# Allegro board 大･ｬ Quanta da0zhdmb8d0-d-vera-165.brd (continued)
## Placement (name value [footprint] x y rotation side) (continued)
PC1239  22u/6.3V_6  [C0603]  84.5 89.14 270 top
PC1240  22u/6.3V_6  [C0603]  31.72 35.72 315 bottom
PC1241  22u/6.3V_6  [C0603]  34 38.01 315 bottom
PC1242  22u/6.3V_6  [C0603]  32.86 36.86 315 bottom
PC1243  22u/6.3V_6  [C0603]  86.63 87.17 180 top
PC1244  22u/6.3V_6  [C0603]  82.57 89.11 270 bottom
PC1245  22u/6.3V_6  [C0603]  80.86 89.08 270 bottom
PC1246  22u/6.3V_6  [C0603]  86.63 88.68 180 top
PC1247  22u/6.3V_6  [C0603]  131.02 87.97 180 top
PC1248  22u/6.3V_6  [C0603]  129.65 82.42 180 top
PC1249  22u/6.3V_6  [C0603]  170.11 74.59 180 top
PC1250  22u/6.3V_6  [C0603]  149.08 85.71 180 top
PC1251  22u/6.3V_6  [C0603]  54.19 84.48 0 top
PC1252  22u/6.3V_6  [C0603]  54.19 86.08 0 top
PC1253  22u/6.3V_6  [C0603]  54.2 87.51 0 top
PC1254  22u/6.3V_6  [C0603]  60.75 86.19 90 bottom
PC1255  22u/6.3V_6  [C0603]  54.19 82.97 0 top
PC1256  22u/6.3V_6  [C0603]  60.34 89.57 270 top
PC1257  22u/6.3V_6  [C0603]  58.92 89.57 270 top
PC1258  0.1U/16V_4  [C0402]  52.16 22.64 270 bottom
PC1259  0.1U/16V_4  [C0402]  51.73 23.71 270 top
PC1260  0.1U/16V_4  [C0402]  50.68 23.73 270 top
PC1261  0.1U/16V_4  [C0402]  48.04 22.25 180 bottom
PC1262  0.1U/16V_4  [C0402]  46.57 25.67 270 top
PC1263  0.1U/16V_4  [C0402]  46.83 30.39 0 bottom
PC1264  0.1U/16V_4  [C0402]  66.99 70.61 90 top
PC1265  0.1U/16V_4  [C0402]  73.59 84.28 180 top
PC1266  0.1U/16V_4  [C0402]  77.11 77.64 270 top
PC1267  0.1U/16V_4  [C0402]  79.62 65.11 90 top
PC1268  0.1U/16V_4  [C0402]  100.68 33.18 90 top
PC1269  0.1U/16V_4  [C0402]  100.55 35.47 90 top
PC1270  0.1U/16V_4  [C0402]  84.14 57.74 90 top
PC1271  0.1U/16V_4  [C0402]  102.33 93.89 180 bottom
PC1272  0.1U/16V_4  [C0402]  54.96 72.75 270 top
PC1273  0.1U/16V_4  [C0402]  25.62 53.5 180 top
PC1274  0.1U/16V_4  [C0402]  42.51 49.69 270 top
PC1275  0.1U/16V_4  [C0402]  217.39 30.01 180 top
PC1276  0.1U/16V_4  [C0402]  22.45 57.44 0 top
PC1277  *0.1U/16V_4  [C0402]  52.54 19.1 90 top
PC1278  *0.1U/16V_4  [C0402]  49.62 49.56 180 top
PC1279  *0.1U/16V_4  [C0402]  98.39 87.28 0 bottom
PC1280  *0.1U/16V_4  [C0402]  208.63 23.27 90 top
PC1281  0.1u/25V_4  [C0402]  192.17 34.88 270 bottom
PC1282  0.1u/25V_4  [C0402]  198.91 34.64 90 bottom
PC1283  0.1u/25V_4  [C0402]  44.77 29.75 270 top
PC1284  0.1u/25V_4  [C0402]  45.73 32.36 90 top
PC1285  0.1u/25V_4  [C0402]  60.32 69.62 270 bottom
PC1286  0.1u/25V_4  [C0402]  63.85 94.95 180 bottom
PC1287  0.1u/25V_4  [C0402]  81.42 76 90 top
PC1288  0.1u/25V_4  [C0402]  75.83 88.64 180 top
PC1289  0.1u/25V_4  [C0402]  170.28 36.93 180 top
PC1290  0.1u/25V_4  [C0402]  165.72 31.09 90 bottom
PC1291  0.1u/25V_4  [C0402]  175.35 42.07 90 top
PC1292  0.1u/25V_4  [C0402]  55.38 27.81 180 bottom
PC1293  0.1u/25V_4  [C0402]  63.46 22.13 0 top
PC1294  *0.1u/25V_4  [C0402]  184.98 40.19 0 top
PC1295  0.01U/50V_4  [C0402]  194.82 39.49 90 bottom
PC1296  0.01U/50V_4  [C0402]  193.48 36.94 180 bottom
PC1297  0.01U/50V_4  [C0402]  197.95 34.64 270 bottom
PC1298  0.01U/50V_4  [C0402]  50.43 28.47 90 top
PC1299  0.01U/50V_4  [C0402]  83.13 57.74 90 top
PC1300  0.01U/50V_4  [C0402]  83.61 61.68 270 top
PC1301  0.01U/50V_4  [C0402]  52.44 68.66 180 top
PC1302  0.01U/50V_4  [C0402]  102.33 92.87 180 bottom
PC1303  0.01U/50V_4  [C0402]  53.43 72.55 180 top
PC1304  0.01U/50V_4  [C0402]  27.78 56.68 90 top
PC1305  0.01U/50V_4  [C0402]  41.24 49.69 270 top
PC1306  0.01U/50V_4  [C0402]  213.96 26.83 0 top
PC1307  0.01U/50V_4  [C0402]  217.39 26.83 180 top
PC1308  0.01U/50V_4  [C0402]  213.33 29.5 90 top
PC1309  0.01U/50V_4  [C0402]  20.92 55.02 0 top
PC1310  0.01U/50V_4  [C0402]  23.33 53.55 0 top
PC1311  0.01U/50V_4  [C0402]  24.35 57.44 0 top
PC1312  *0.01U/50V_4  [C0402]  50 52.1 180 top
PC1313  1U/6.3V_4  [C0402]  48.35 24.54 270 top
PC1314  1U/6.3V_4  [C0402]  48.49 28.47 90 top
PC1315  1U/6.3V_4  [C0402]  61.74 73.03 90 top
PC1316  1U/6.3V_4  [C0402]  74.44 78.62 0 top
PC1317  1U/6.3V_4  [C0402]  63.21 81.74 270 bottom
PC1318  1U/6.3V_4  [C0402]  200.94 36.29 180 top
PC1319  1U/6.3V_4  [C0402]  104.87 35.85 90 top
PC1320  10u/6.3V_4  [C0402_2]  74.16 77.3 0 top
PC1321  10u/6.3V_4  [C0402_2]  69.31 70.39 0 top
PC1322  10u/6.3V_4  [C0402_2]  62.07 85.76 270 bottom
PC1323  10u/6.3V_4  [C0402_2]  71.98 83.24 90 top
PC1324  10u/6.3V_4  [C0402_2]  68.19 73.31 180 top
PC1325  10u/6.3V_4  [C0402_2]  63.16 79.74 270 bottom
PC1326  22nF/16V_4  [C0402]  54.77 25.8 180 top
PC1327  *22nF/16V_4  [C0402]  192.06 41.99 90 bottom
PC1328  *22nF/16V_4  [C0402]  193.07 41.98 90 bottom
PC9091  270p/50V_4  [C0402]  191.97 33.15 90 bottom
PC9093  470p/50V_4  [C0402]  192.36 32.32 90 top
PC9094  470p/50V_4  [C0402]  52.28 26.12 180 top
PC9095  470p/50V_4  [C0402]  189.22 39.5 270 top
PC9096  470p/50V_4  [C0402]  199.16 43.61 270 bottom
PC9097  2200P/50V_4  [C0402]  195.39 41.37 180 bottom
PC9098  2200P/50V_4  [C0402]  189.92 33.98 90 bottom
PC9099  2200P/50V_4  [C0402]  195.06 34.64 90 bottom
PC9100  4.7uF/10V_4  [C0402_2]  172.51 39.26 180 bottom
PC9101  4.7uF/10V_4  [C0402_2]  159.32 31.26 270 top
PC9102  4.7uF/10V_4  [C0402_2]  178.23 38.01 90 bottom
PC9103  *4.7uF/10V_4  [C0402_2]  187.26 38.81 270 top
PC9104  47P/50V_4  [C0402]  193.48 37.9 180 bottom
PC9105  47P/50V_4  [C0402]  196.74 39.49 90 bottom
PC9106  33P/50V_4  [C0402]  196.02 34.64 270 bottom
PC9107  0.15U/10V_4  [C0402]  200.84 32.07 90 top
PC9108  0.18U/10V_4  [C0402]  190.15 32.43 180 top
PC9109  0.18U/10V_4  [C0402]  194.62 42.65 0 top
PC9110  0.22u/10V_4  [C0402]  69.56 72.04 270 top
PC9111  0.47u/6.3V_4  [C0402]  77.54 82.02 270 bottom
PC9112  2.2u/10V_4  [C0402]  70.99 71.89 90 top
PC9113  2.2u/10V_4  [C0402]  73.6 81.16 90 top
PC9114  2.2u/10V_4  [C0402]  60.72 73.03 90 top
PC9115  3300P/50V_4  [C0402]  193.48 38.86 180 bottom
PC9116  3300P/50V_4  [C0402]  199.11 41.19 180 bottom
PC9117  330P/50V_4  [C0402]  193.48 39.83 180 bottom
PC9118  330P/50V_4  [C0402]  193.13 34.64 270 bottom
PC9119  330P/50V_4  [C0402]  198.55 41.6 180 top
PC9120  390P/50V_4  [C0402]  199.23 42.16 0 bottom
PC9121  390P/50V_4  [C0402]  190.79 38.93 180 bottom
PC9122  4700p/25V_4  [C0402]  56.28 29.93 180 bottom
PC9123  4700p/25V_4  [C0402]  199.62 39.49 270 bottom
PC9124  *15u/25V_7343H1.0  [CC7343]  183.23 30.89 270 bottom
PD1  *PDZ5.6B  [DSM]  70.96 19.85 0 top
PD2  *PDZ5.6B  [DSM]  70.96 21.88 0 top
PD3  P4SMAFJ20A  [D-3_8X2_5]  28.92 68.74 90 bottom
PD4  BAT54CW  [UMT_213-3-1_3]  48.81 32.63 0 bottom
PJ2  50458-00801-V02_Header  [50458-00801-V02-8P-L]  66.39 15.65 180 bottom
PL1  0.47uH_7x7x3  [CHOKE-PCMC063T-3R3MN-SMT]  73.18 67.34 0 bottom
PL2  1uH_7x7x3  [CHOKE-PCMC063T-3R3MN-SMT]  57.33 81.41 180 bottom
PL3  2.2uH_7x7x3  [CHOKE-PCMC063T-3R3MN-SMT]  47.62 17.25 90 bottom
PL4  0.15uH_7x7x3  [CHOKE-PCMC063T-3R3MN-SMT]  160.97 38.04 180 bottom
PL5  0.15uH_7x7x3  [CHOKE-PCMC063T-3R3MN-SMT]  177.29 49.52 90 bottom
PL6  *0.15uH_7x7x3  [CHOKE-PCMC063T-3R3MN-SMT]  185.36 49.11 90 bottom
PL7  0.68uH_7x7x3  [CHOKE-PCMC063T-3R3MN-SMT]  152.31 30.96 180 bottom
PL8  2.2uH_7x7x3  [CHOKE-PCMC063T-3R3MN-SMT]  57.27 90.94 0 bottom
PL9  1uH_7x7x3  [CHOKE-PCMC063T-3R3MN-SMT]  69.53 89.67 270 bottom
PL10  2.2uH_7x7x3  [CHOKE-PCMC063T-3R3MN-SMT]  81.42 83.16 270 bottom
PQ1  TPCA8109  [POWER-5X5-1_27-5P]  60.9 27.87 180 bottom
PQ2  CSD87330Q3D  [SON8-3_3X3_3]  53 15.19 0 bottom
PQ3  CSD87330Q3D  [SON8-3_3X3_3]  44.14 24.52 0 bottom
PQ129  PJA138K  [SOT23_213-3_3-2]  27.27 60.1 180 top
PQ130  AO3402  [SOT23_213-3_3-2]  32.73 70.26 0 top
PR1  0.01_1%_0612  [RC3216]  57.22 23.53 0 bottom
PR2  0.02_1%_0612  [RC3216]  42.64 32.37 180 bottom
PR3  2.2_5%_6  [R0603]  177.54 44.8 180 top
PR4  *2.2_5%_6  [R0603]  185.83 44.28 180 top
PR5  2.2_5%_6  [R0603]  165.32 37.56 270 top
PR6  *SHORT_2  [S0201]  69.32 22.34 270 bottom
PR7  *SHORT_2  [S0201]  67.34 22.33 270 bottom
PR8  *0_5%_4  [R0402]  31.97 60.05 180 top
PR9  *SHORT_4  [S0402]  178.66 75.22 0 bottom
PR10  *SHORT_4  [S0402]  193.21 41.99 90 top
PR11  *SHORT_4  [S0402]  192.25 41.99 90 top
PR12  1K_1%_4  [R0402]  199.49 31.78 180 bottom
PR13  *2.2_5%_6  [R0603]  42.79 21.8 180 bottom
PR14  150/F_4  [R0402]  185.77 74.79 0 bottom
PR15  30K_1%_4  [R0402]  177.51 82.46 0 bottom
PR19  *10K_1%_4  [R0402]  77.57 87.47 270 top
PR20  100K_1%_4  [R0402]  54.34 32.47 180 bottom
PR21  *SHORT_4  [S0402]  62.3 75.55 270 top
PR22  *100K_1%_4  [R0402]  53.71 28.85 0 top
PR23  *SHORT_2  [S0201]  60.24 83.83 180 top
PR24  *SHORT_2  [S0201]  57.3 86.73 90 top
PR25  *SHORT_2  [S0201]  57.26 85.39 270 top
PR26  *SHORT_2  [S0201]  67.05 94.85 90 top
PR27  *SHORT_2  [S0201]  66.29 94.84 90 top
PR28  *SHORT_2  [S0201]  78.03 86.12 0 top
PR29  *SHORT_2  [S0201]  77.13 86.06 90 top
PR30  *SHORT_2  [S0201]  73.75 70.45 270 top
PR31  *SHORT_2  [S0201]  72.31 70.44 270 top
PR32  *SHORT_2  [S0201]  102.84 87.28 90 bottom
PR33  *SHORT_4  [S0402]  198.92 32.07 90 top
PR34  *SHORT_4  [S0402]  190.15 34.35 0 top
PR35  *SHORT_4  [S0402]  172.87 36.78 180 bottom
PR36  *SHORT_4  [S0402]  64.48 78.77 0 top
PR37  *SHORT_4  [S0402]  98.01 93 180 bottom
PR38  *SHORT_4  [S0402]  76.27 85.05 0 top
PR39  *SHORT_4  [S0402]  73.07 82.94 270 top
PR40  *SHORT_4  [S0402]  47.59 46.77 0 top
PR41  *SHORT_4  [S0402]  78.96 72.8 180 top
PR42  *SHORT_4  [S0402]  200.75 40.67 180 top
PR43  *SHORT_4  [S0402]  54.46 29.62 0 bottom
PR44  *SHORT_4  [S0402]  52 30.99 90 bottom
PR45  *SHORT_4  [S0402]  51.02 30.99 90 bottom
PR46  *SHORT_4  [S0402]  52.98 31 90 bottom
PR47  *SHORT_4  [S0402]  53.95 30.99 90 bottom
PR48  *SHORT_4  [S0402]  68.17 72.12 0 top
PR49  *SHORT_4  [S0402]  177.01 38.98 0 top
PR50  *SHORT_4  [S0402]  69.82 69.25 0 top
PR51  *SHORT_4  [S0402]  65.02 73.31 270 top
PR52  *SHORT_4  [S0402]  69.82 67.09 0 top
PR53  *SHORT_4  [S0402]  66.72 77.48 90 top
PR54  *SHORT_4  [S0402]  68.93 83.35 90 top
PR55  *SHORT_4  [S0402]  104.49 31.02 0 top
PR56  *SHORT_4  [S0402]  196.94 43.72 90 top
PR57  *SHORT_4  [S0402]  195.98 43.72 90 top
PR58  *SHORT_4  [S0402]  189.66 36.88 0 top
PR59  *SHORT_4  [S0402]  189.66 35.92 0 top
PR60  *SHORT_4  [S0402]  196.02 31.34 270 top
PR61  *SHORT_4  [S0402]  197 31.33 270 top
PR62  *SHORT_4  [S0402]  81.07 66.33 180 top
PR63  *SHORT_4  [S0402]  200.74 39.18 180 top
PR64  *SHORT_4  [S0402]  74.47 82.94 180 top
PR65  *SHORT_4  [S0402]  177.15 37.5 90 bottom
PR66  *SHORT_4  [S0402]  77.33 79.05 180 top
PR67  *SHORT_4  [S0402]  73.34 85.26 0 top
PR68  *SHORT_4  [S0402]  63.34 85.76 270 top
PR69  *SHORT_4  [S0402]  67.41 69.14 180 top
PR70  *SHORT_4  [S0402]  165.59 29.29 90 top
PR71  *0_5%_4  [R0402]  82.92 66.33 180 top
PR72  *0_5%_4  [R0402]  102.58 31.02 180 top
PR73  *0_5%_4  [R0402]  104.49 29.88 0 top
PR74  *0_5%_4  [R0402]  76.75 74.43 90 top
PR75  *0_5%_4  [R0402]  64.89 75.7 0 top
PR76  *0_5%_4  [R0402]  64.99 74.71 0 top
PR77  *0_5%_4  [R0402]  64.71 77.81 180 top
PR78  *0_5%_4  [R0402]  46.32 48.29 90 top
PR79  *0_5%_4  [R0402]  99.66 88.43 0 bottom
PR80  *0_5%_4  [R0402]  99.66 90.46 0 bottom
PR81  *0_5%_4  [R0402]  99.66 89.44 0 bottom
PR82  *0_5%_4  [R0402]  217.39 27.85 0 top
PR83  *0_5%_4  [R0402]  45.23 48.32 90 top
PR84  *0_5%_4  [R0402]  185.43 37.29 270 bottom
PR85  *0_5%_4  [R0402]  191.25 44.06 90 bottom
PR86  *0_5%_4  [R0402]  52.42 49.31 0 top
PR87  *0_5%_4  [R0402]  52.42 51.85 0 top
PR88  *0_5%_4  [R0402]  52.42 48.29 0 top
PR89  *0_5%_4  [R0402]  52.42 50.33 0 top
PR90  *SHORT_4  [S0402]  74.77 75.47 180 top
PR91  0_5%_4  [R0402]  195.21 44.44 90 bottom
PR92  100K_1%_4  [R0402]  52.36 28.47 90 top
PR93  *100K_1%_4  [R0402]  193.17 44.06 90 bottom
PR94  *100K_1%_4  [R0402]  196.57 45.06 180 bottom
PR95  *100K_1%_4  [R0402]  192.21 44.06 90 bottom
PR96  *100K_1%_4  [R0402]  192.06 44.07 90 top
PR97  100K_1%_4  [R0402]  21.43 53.5 0 top
PR98  100K_1%_4  [R0402]  26.76 65.06 270 top
PR99  100K_1%_4  [R0402]  35.65 70.26 180 top
PR100  100K_1%_4  [R0402]  63.9 70.95 180 top
PR101  100K_1%_4  [R0402]  75.66 74.1 90 top
PR102  100K_1%_4  [R0402]  60.5 70.57 270 top
PR103  100K_1%_4  [R0402]  62.43 77.76 90 top
PR104  100K_1%_4  [R0402]  62.37 70.77 270 top
PR105  100K_1%_4  [R0402]  76.45 83.78 0 top
PR106  100K_1%_4  [R0402]  76.45 82.79 0 top
PR107  100K_1%_4  [R0402]  63.34 83.98 90 top
PR108  100K_1%_4  [R0402]  71.09 85.5 90 top
PR109  100K_1%_4  [R0402]  69.94 85.5 90 top
PR110  100K_1%_4  [R0402]  51.4 28.47 270 top
PR111  100K_1%_4  [R0402]  68.42 85.73 180 top
PR112  *100/F_4  [R0402]  189.48 36.64 0 bottom
PR113  *100/F_4  [R0402]  193.51 35.98 0 bottom
PR114  *100/F_4  [R0402]  196.99 34.64 90 bottom
PR115  *100/F_4  [R0402]  193.7 31.79 0 top
PR116  *100/F_4  [R0402]  195.78 39.49 270 bottom
PR117  *100/F_4  [R0402]  197.91 43.94 270 top
PR118  100/F_4  [R0402]  202.91 34.7 270 top
PR119  100/F_4  [R0402]  65.54 23.45 270 bottom
PR120  1.1K_1%_4  [R0402]  197.43 33.29 180 bottom
PR121  1.1K_1%_4  [R0402]  190.82 35.75 90 bottom
PR122  1.1K_1%_4  [R0402]  193.02 44.07 270 top
PR123  *1.1K_1%_4  [R0402]  194.62 44.59 0 top
PR124  1_1%_4  [R0402]  45.46 31.92 0 bottom
PR125  1_1%_4  [R0402]  45.46 32.9 0 bottom
PR126  1_1%_4  [R0402]  54.12 23.71 180 bottom
PR127  1_1%_4  [R0402]  54.1 22.69 180 bottom
PR128  1_1%_4  [R0402]  47.21 28.55 270 top
PR129  1K_1%_4  [R0402]  196.19 43.7 90 bottom
PR130  1K_1%_4  [R0402]  190.18 39.5 270 top
PR131  1K_1%_4  [R0402]  189.96 32.64 0 bottom
PR132  1K_1%_4  [R0402]  62.58 82.2 180 top
PR133  1K_1%_4  [R0402]  54.77 26.78 0 top
PR134  1K_1%_4  [R0402]  78.22 71.51 0 top
PR135  1M_5%_4  [R0402]  76.47 80.65 180 top
PR136  *1M_5%_4  [R0402]  69.94 83.35 270 top
PR137  10K_1%_4  [R0402]  27.27 69.88 90 top
PR138  10K_1%_4  [R0402]  77.13 72.63 0 top
PR139  10K/F_4_3435NTC  [R0402]  173.27 46.93 270 bottom
PR140  10K/F_4_3435NTC  [R0402]  162.59 33.99 180 bottom
PR141  10K/F_4_3435NTC  [R0402]  156.81 28.02 180 bottom
PR142  10K_5%_4  [R0402]  191.16 38.36 270 top
PR143  10K_5%_4  [R0402]  197.08 41.99 90 top
PR144  11K_1%_4  [R0402]  199.88 32.07 90 top
PR145  11K_1%_4  [R0402]  194.62 43.61 180 top
PR146  11K_1%_4  [R0402]  190.15 31.46 0 top
PR147  13K_1%_4  [R0402]  66.85 82.96 180 top
PR148  13K_1%_4  [R0402]  65.96 70.85 90 top
PR149  2K_1%_4  [R0402]  197.63 43.12 180 bottom
PR150  2K_1%_4  [R0402]  193.7 32.75 0 top
PR151  2K_1%_4  [R0402]  197.51 42.16 180 bottom
PR152  2K_1%_4  [R0402]  194.22 43.04 90 bottom
PR153  2K_1%_4  [R0402]  190.79 37.97 180 bottom
PR154  2K_1%_4  [R0402]  189.48 35.68 0 bottom
PR155  2K_1%_4  [R0402]  196.62 32.29 0 bottom
PR156  2K_1%_4  [R0402]  193.78 33.01 0 bottom
PR157  63.4K_1%_4  [R0402]  200.93 34.32 180 top
PR158  10/F_4  [R0402]  202.79 36.61 90 top
PR159  2.49K_1%_4  [R0402]  197.39 41.19 0 bottom
PR160  300K_1%_4  [R0402]  28.19 65.62 180 top
PR161  4.7_4  [R0402]  48.48 31.02 270 top
PR162  470K_4_4700NTC  [R0402]  173.27 48.65 90 bottom
PR163  470K_4_4700NTC  [R0402]  160.83 33.99 180 bottom
PR164  49.9/F_4  [R0402]  202.53 38.39 180 top
PR165  8.25K/F_4  [R0402]  198.66 39.49 270 bottom
PR166  105K/F_4  [R0402]  194.09 34.64 90 bottom
PR167  165K/F_4  [R0402]  200.94 35.32 0 top
PR168  1.47K/F_4  [R0402]  195.05 31.71 90 top
PR169  3.65K/F_4  [R0402]  195.54 33.29 0 bottom
PR170  9.1K/F_4  [R0402]  66.51 85.5 0 top
PR171  604/F_4  [R0402]  35.65 69.12 180 top
PR172  2.21K/F_4  [R0402]  197.63 44.08 180 bottom
PR173  604/F_4  [R0402]  199.49 32.74 0 bottom
PR174  45.3/F_4  [R0402]  204.44 36.36 180 top
PR175  27.4K/F_4  [R0402]  190.79 40.18 0 bottom
PR176  27.4K/F_4  [R0402]  49.46 28.47 270 top
PR177  27.4K/F_4  [R0402]  198.54 42.57 0 top
PR178  162K/F_4  [R0402]  52.28 27.09 180 top
PR179  90.9K/F_4  [R0402]  49.62 31.02 270 top
PR180  249K/F_4  [R0402]  76.47 81.67 180 top
PR181  576/F_4  [R0402]  195.21 42.72 90 bottom
PR182  93.1K/F_4  [R0402]  197.7 39.49 270 bottom
PR183  2.87K/F_4  [R0402]  191.79 36.62 90 bottom
PR184  1.65K/F_4  [R0402]  189.72 38.16 180 top
PR185  97.6K/F_4  [R0402]  192.13 38.73 90 bottom
PR186  536/F_4  [R0402]  190.88 33.98 270 bottom
PR187  7.5K/F_4  [R0402]  75.07 80.63 90 top
PR188  8.06K/F_4  [R0402]  72.53 73.85 0 top
PR189  *SHORT_2  [S0201]  58.38 84.14 180 top
PR190  *2.2_5%_6  [R0603]  156.51 31.41 90 top
PU1  TMP708AIDBVR  [SOT23-5-2_8-95-5P-G708]  182.34 74.46 180 bottom
PU2  FPF2495UCX  [BGA9-FAIRCHILD-FPF2495UCX]  31.46 66.71 90 top
PU3  NX20P5090UK  [BGA15-NXP-NX20P5090UK]  30.83 62.82 0 top
PU4  ISL9237HRZ-T  [QFN32-4X4-4-33P-ISL95853]  49.98 26.17 180 bottom
PU5  ISL95857HRTZ-T  [QFN40-5X5-4-41P-ISL62771-SMT]  196 37.05 180 top
PU6  SIC532CD-T1-GE3  [POWER-4_5X3_5-5-13P]  168.56 37.49 270 bottom
PU7  SIC532CD-T1-GE3  [POWER-4_5X3_5-5-13P]  177.52 42.03 180 bottom
PU8  *SIC532CD-T1-GE3  [POWER-4_5X3_5-5-13P]  186.38 41.11 180 bottom
PU9  ISL95808HRZ-T  [DFN8-2X2-5-9P-ISL6208BCRZ]  163.1 30.35 90 top
PU10  SIZ340DT-T1-GE3  [POWER-3X3-65-10P-0_8H]  159.2 30.22 180 bottom
PU11  SN74AUP1G97DCKR  [SC70-2_1-65-6P-SN74AVC1T45]  103.47 32.8 0 top
PU12  SLG5NT1477VTR  [TDFN9-2X1_5-4]  102.46 35.72 90 top
PU13  *SLG5NT1477VTR  [TDFN9-2X1_5-4]  100.93 86.65 270 bottom
PU14  SLG5NT1477VTR  [TDFN9-2X1_5-4]  81.12 58.88 270 top
PU15  SN74AUP1G97DCKR  [SC70-2_1-65-6P-SN74AVC1T45]  82.09 64.6 0 top
PU16  SLG5NT1477VTR  [TDFN9-2X1_5-4]  81.7 61.81 270 top
PU17  *SLG7NT402VTR  [TDFN8-2X1_5-5-6P]  47.34 51.47 270 top
PU18  SLG7NT402VTR  [TDFN8-2X1_5-5-6P]  100.17 93.12 90 bottom
PU19  SLG5NT1477VTR  [TDFN9-2X1_5-4]  44.42 51.72 180 top
PU20  SLG5NT1477VTR  [TDFN9-2X1_5-4]  26 55.41 180 top
PU21  SLG7NT402VTR  [TDFN8-2X1_5-5-6P]  215.23 28.61 0 top
PU22  SLG7NT402VTR  [TDFN8-2X1_5-5-6P]  23.08 55.28 90 top
PU23  SLG7NT402VTR  [TDFN8-2X1_5-5-6P]  53.18 70.77 0 top
PU50  *SN74LVC1G08DCKR  [SC70-2_1-65-5P]  203.55 23.27 180 top
PU51  AOZ1331DI  [SON14-3X2-4-15P-SMT]  207.87 26.83 0 top
PU3044  CSD87381P  [LGA5-3X2_7]  63.49 88.65 180 bottom
PU3045  CSD87381P  [LGA5-3X2_7]  66.82 69.48 270 bottom
PU3047  CSD87381P  [LGA5-3X2_7]  74.72 86.24 180 bottom
PU3048  CSD87381P  [LGA5-3X2_7]  79 76.77 90 bottom
PU3254  TPS650830ZCGR  [BGA159-TEXAS-TPS650830]  70.22 77.94 270 bottom
Q5  MMBT3904-7-F  [SOT23_213-3_3-2]  181.7 70.52 0 bottom
Q10  AP2331SA-7  [SOT23_213-3_3-2]  22.32 50.58 180 bottom
Q105  PJA3413  [SOT23_213-3_3-2]  98.46 82.32 90 bottom
Q109  DTC144EU  [UMT_213-3-1_3]  13.81 73.82 0 top
Q110  DTC144EU  [UMT_213-3-1_3]  10.25 73.82 0 top
Q111  PJA138K  [SOT23_213-3_3-2]  49.5 49.44 270 bottom
Q112  PJA3434  [SOT23_213-3_3-2]  17.11 13.11 0 bottom
Q113  2N7002K  [SOT23_213-3_3-2]  188.31 19.21 180 top
Q114  PJA3434  [SOT23_213-3_3-2]  16.98 8.29 90 bottom
Q121  DDTC144EUA-7-F  [UMT_213-3-1_3]  10.63 81.69 0 top
Q125  DDTC144EUA-7-F  [UMT_213-3-1_3]  10.63 78.65 0 top
Q127  FDV301N  [SOT23_213-3_3-2]  188.05 23.15 0 top
Q129  *FDV301N  [SOT23_213-3_3-2]  17.52 20.73 0 bottom
Q135  2N7002K  [SOT23_213-3_3-2]  157.65 22.39 180 top
Q136  PJA3434  [SOT23_213-3_3-2]  17.49 16.92 0 bottom
Q137  2N7002KDW  [SOT363-2_1-65-6P]  48.86 63.03 0 top
Q139  2N7002K  [SOT23_213-3_3-2]  39.21 59.72 270 top
QAP1009  2N7002K  [SOT23_213-3_3-2]  70.96 60.74 180 top
QCP4007  PJA3434  [SOT23_213-3_3-2]  25.11 32.16 90 top
QCP4009  MMBT3904-7-F  [SOT23_213-3_3-2]  37.81 22.21 90 bottom
QCP4010  MMBT3904-7-F  [SOT23_213-3_3-2]  101.31 37.37 90 bottom
QCP4011  *MMBT3904-7-F  [SOT23_213-3_3-2]  79.62 20.25 0 bottom
QCP4112  PJA3434  [SOT23_213-3_3-2]  32.48 31.66 0 top
QPM3251  2N7002K  [SOT23_213-3_3-2]  72.1 33.87 0 bottom
QPM3360  2N7002K  [SOT23_213-3_3-2]  92.8 39.53 180 bottom
QPM3362  2N7002K  [SOT23_213-3_3-2]  166.59 22.89 0 bottom
QPM3371  2N7002K  [SOT23_213-3_3-2]  85.18 29.62 90 bottom
QPM3372  PJA3434  [SOT23_213-3_3-2]  81.29 28.42 90 bottom
QPM3373  PJA3434  [SOT23_213-3_3-2]  77.48 28.42 90 bottom
QPM3374  PJA3434  [SOT23_213-3_3-2]  73.75 28.48 270 bottom
QPM3382  2N7002K  [SOT23_213-3_3-2]  69.31 36.61 270 bottom
QPM3383  PJA3434  [SOT23_213-3_3-2]  19.91 51.05 90 top
QPM3384  PJA3434  [SOT23_213-3_3-2]  16.1 51.05 90 top
QPM3387  2N7002K  [SOT23_213-3_3-2]  74.97 39.15 180 top
QPM3388  FDV301N  [SOT23_213-3_3-2]  90.04 68.66 270 top
QPM3389  *2N7002K  [SOT23_213-3_3-2]  118.2 20.86 180 top
QPM3390  PJA138K  [SOT23_213-3_3-2]  96.43 91.33 270 bottom
QPM3391  2N7002K  [SOT23_213-3_3-2]  95.47 36.48 90 bottom
R1A1  *10K_4  [R0402]  27.78 18.32 90 top
R1A2  10K_4  [R0402]  27.78 16.54 90 top
R1A3  *SHORT_6  [S0603]  32.73 15.91 90 top
R1A4  *SHORT_6  [S0603]  31.21 15.91 90 top
R1A4PD1  100K/F_4  [R0402]  77.94 40.42 90 top
R1A5  *SHORT_6  [S0603]  37.94 15.53 270 top
R1A6  *SHORT_6  [S0603]  36.4 15.49 270 top
R1B26  *100K/F_4  [R0402]  18.2 18.52 0 top
R1B27  *0_4  [R0402]  39.57 24.85 270 top
R1B28  *0_4  [R0402]  34.26 23.91 270 top
R1B30  *0_4  [R0402]  36.92 26.45 90 top
R1B32  100K/F_4  [R0402]  15.71 11.46 90 bottom
R1B33  100K/F_4  [R0402]  19.14 21.5 90 top
R1C5  *SHORT_4  [S0402]  15.71 17.18 90 top
R1C10  *1M_4  [R0402]  152.44 20.28 180 top
R1C11  *SHORT_4  [S0402]  18.53 60.13 180 bottom
R1C12  *SHORT_4  [S0402]  18.53 59.11 180 bottom
R1D4  210K_4  [R0402]  36.92 24.67 270 top
R1D7  1K/F_4  [R0402]  16.86 19.08 270 top
R1D9  4.7_4  [R0402]  18.25 11.46 270 top
R1D10  4.7_4  [R0402]  18.71 9.3 270 top
R1D11  *SHORT_4  [S0402]  38.42 24.85 270 top
R1D12  *SHORT_4  [S0402]  33.11 23.91 270 top
R1D13  2K/F_4  [R0402]  31.46 23.53 0 top
R1D18  *0_4  [R0402]  15.71 21.5 90 top
R1D19  *200K_4  [R0402]  16.86 21.5 90 top
R1D21  *300_4  [R0402]  19.7 9.3 270 top
R1D22  *300_4  [R0402]  17.49 12.99 180 top
R1M4  30K/F_4  [R0402]  204.18 19.97 90 top
R1M5  48.7K_4  [R0402]  205.33 19.97 90 top
R2B2  *10K_4  [R0402]  15.71 23.53 270 top
R8A16  *SHORT_6  [S0603]  34.26 61.25 90 top
R11  *SHORT_6  [S0603]  43.4 60.74 0 top
R41  *10K/F_4  [R0402]  23.08 29.75 180 top
R45  49.9_4  [R0402]  100.3 73.45 270 bottom
R46  49.9_4  [R0402]  99.28 73.44 270 bottom
R47  49.9_4  [R0402]  140 52.03 270 top
R48  49.9_4  [R0402]  139.03 51.98 270 top
R49  *49.9_4  [R0402]  143.57 38.94 270 bottom
R56  10K_4  [R0402]  155.24 19.64 0 top
R59  *0_6  [R0603]  18.76 23.91 90 top
R66  1K/F_4  [R0402]  150.64 41.99 0 bottom
R88  1K_2  [R0201]  144.42 38.92 90 bottom
R129  *49.9_4  [R0402]  140.89 39.53 0 bottom
R130  *49.9_4  [R0402]  141.32 39.56 270 top
R131  *49.9_4  [R0402]  140.86 40.5 0 bottom
R132  49.9_4  [R0402]  137.93 39.41 0 top
R133  49.9_4  [R0402]  138.73 37.35 270 top
R134  49.9_4  [R0402]  139.29 39.07 270 top
R136  49.9_4  [R0402]  136.58 39.73 90 top
R138  49.9_4  [R0402]  140.96 40.9 180 top
R217  *1K_2  [R0201]  97.87 73.83 270 bottom
R338  *4.7K_4  [R0402]  48.48 65.82 180 top
R346  *4.7K_4  [R0402]  49.24 59.85 0 top
R527  *SHORT_4  [S0402]  13.68 51.85 270 bottom
R529  20K_4  [R0402]  14.7 51.85 270 bottom
R619  100K/F_4  [R0402]  46.96 58.07 270 bottom
R679  5.9K/F_4  [R0402]  15.84 48.39 180 bottom
R680  2K/F_4  [R0402]  18.23 42.93 0 bottom
R681  10K_4  [R0402]  23.11 39.53 270 top
R682  10K_4  [R0402]  21.84 39.53 270 top
R687  4.7K_4  [R0402]  17.34 49.26 90 bottom
R739  100K/F_4  [R0402]  42.64 58.96 90 top
R771  *SHORT_4  [S0402]  52.04 58.2 90 bottom
R772  *SHORT_4  [S0402]  53.18 58.2 90 bottom
R788  33_4  [R0402]  44.67 58.07 90 bottom
R790  33_4  [R0402]  164.05 22.51 90 bottom
R851  33_4  [R0402]  23.59 20.66 90 top
R865  33_4  [R0402]  79.77 56.22 90 top
R866  33_4  [R0402]  70.58 57.31 90 bottom
R868  33_4  [R0402]  82.64 56.8 0 bottom
R869  33_4  [R0402]  70.45 55.28 180 bottom
R870  33_4  [R0402]  76.22 55.99 180 top
R872  10K_4  [R0402]  181.96 68.11 180 bottom
R873  10K_4  [R0402]  184.5 70.14 270 bottom
R874  10K_4  [R0402]  183.86 68.11 0 bottom
R877  2.2K_4  [R0402]  92.27 48.57 90 bottom
R879  2.2K_4  [R0402]  99.66 41.82 90 bottom
R888  33_4  [R0402]  64.23 55.41 0 top
R889  33_4  [R0402]  64.23 60.99 0 top
R890  33_4  [R0402]  64.23 57.44 0 top
R891  *249K_4  [R0402]  92.93 70.52 0 bottom
R892  *10K_4  [R0402]  97.05 53.3 270 bottom
R894  10K_2  [R0201]  103.23 75.39 0 top
R895  100K_2  [R0201]  77.82 48.67 180 bottom
R896  1K_2  [R0201]  68.8 56.01 90 top
R899  33_4  [R0402]  105.12 40.93 270 top
R900  33_4  [R0402]  102.81 41.31 270 bottom
R936  100K/F_4  [R0402]  25.62 69.88 90 top
R956  *SHORT_6  [S0603]  46.07 55.91 270 top
R957  *SHORT_4  [S0402]  47.97 45.37 180 bottom
R958  *SHORT_4  [S0402]  63.52 57.06 90 bottom
R960  *SHORT_4  [S0402]  59.28 52.87 270 top
R964  *SHORT_4  [S0402]  173.07 26.83 270 top
R977  *SHORT_4  [S0402]  39.72 50.71 0 top
R979  5.11K_4  [R0402]  14.09 53.2 0 bottom
R980  30.9K_4  [R0402]  35.02 43.98 270 top
R981  5.11K_4  [R0402]  34 43.98 90 top
R982  60.4/F_4  [R0402]  28.41 53.75 180 top
R983  150/F_4  [R0402]  17.34 53.91 180 bottom
R984  5.11K_4  [R0402]  17.37 53.75 180 top
R985  30.9K_4  [R0402]  26 51.34 90 top
R986  5.11K_4  [R0402]  26.97 51.72 270 top
R987  60.4/F_4  [R0402]  28.41 52.74 180 top
R988  150/F_4  [R0402]  28.41 50.58 180 top
R999  75K/F_4  [R0402]  31.59 57.44 180 top
R1000  15K/F_4  [R0402]  30.83 55.15 180 top
R1002  *SHORT_4  [S0402]  39.72 51.85 0 top
R1022  180K/F_4  [R0402]  73.37 38.39 180 bottom
R1023  20K_2  [R0201]  75.79 39.02 270 bottom
R1040  SP@100K_2  [R0201]  94.33 60.61 180 bottom
R1041  SP@100K_2  [R0201]  93.95 61.5 180 bottom
R1042  SP@100K_2  [R0201]  94.33 59.85 180 bottom
R1043  SP@100K_2  [R0201]  94.71 58.96 90 bottom
R1044  SP@100K_2  [R0201]  95.47 60.61 180 bottom
R1045  SP@100K_2  [R0201]  95.22 61.5 270 bottom
R1046  SP@100K_2  [R0201]  95.47 59.85 180 bottom
R1047  SP@100K_2  [R0201]  95.47 58.96 90 bottom
R1048  *SHORT_2  [S0201]  95.34 39.4 270 bottom
R1049  *100K_2  [R0201]  83.15 45.88 270 top
R1050  100K_2  [R0201]  82.39 45.88 270 top
R1051  *100K_2  [R0201]  86.07 33.31 90 bottom
R1052  100K_2  [R0201]  83.53 43.85 0 top
R1053  *100K_2  [R0201]  82.52 43.85 180 top
R1054  100K_2  [R0201]  85.31 33.31 270 bottom
R1056  113/F_4  [R0402]  97.52 55.2 180 bottom
R1064  *2.2K_4  [R0402]  102.96 41.38 180 top
R1071  *SHORT_2  [S0201]  75.1 43.42 0 top
R1074  *SHORT_4  [S0402]  77.31 38.13 90 top
R1075  *10K_2  [R0201]  78.33 37.5 90 top
R1076  *SHORT_4  [S0402]  69.31 32.93 0 bottom
R1082  100K_2  [R0201]  27.78 33.82 270 top
R1084  100K_2  [R0201]  32.73 54.9 0 top
R1085  560_4  [R0402]  13.05 76.23 270 top
R1086  1K/F_4  [R0402]  12.03 76.23 90 top
R1097  *4.7K/J_4  [R0402]  98.04 53.3 270 bottom
R1104  *SHORT_2  [S0201]  74.77 42.71 0 bottom
R1105  *SHORT_4  [S0402]  64.23 54.14 180 top
R1106  33_4  [R0402]  99.18 38.54 270 top
R1109  *SHORT_2  [S0201]  83.91 45.88 90 top
R1113  100K_2  [R0201]  98.45 72.69 270 top
R1115  *SHORT_2  [S0201]  133.56 73.52 90 bottom
R1116  *SHORT_2  [S0201]  135.52 71.98 0 top
R1117  *0_2  [R0201]  133.56 74.97 270 bottom
R1118  *SHORT_2  [S0201]  130.34 73.43 180 top
R1119  *SHORT_2  [S0201]  131.12 71.78 90 bottom
R1120  *0_2  [R0201]  128.62 62.01 270 top
R1124  0_4  [R0402]  20.92 20.73 270 bottom
R1129  49.9K/F_4  [R0402]  47.97 46.52 180 bottom
R1131  100K_2  [R0201]  92.74 70.28 90 top
R1134  *100K_2  [R0201]  98.39 40.55 90 bottom
R1138  *0_2  [R0201]  186.78 16.29 0 top
R1139  *SHORT_2  [S0201]  186.78 15.53 180 top
R1141  *100K_2  [R0201]  99.15 52.33 0 bottom
R1142  *100K_2  [R0201]  99.15 53.42 0 bottom
R1143  *100K_2  [R0201]  97.48 55.18 0 top
R1144  100K_2  [R0201]  186.78 14.64 0 top
R1157  100K_2  [R0201]  28.29 27.21 90 bottom
R1158  *SHORT_2  [S0201]  83.28 33.31 270 bottom
R1162  100K_2  [R0201]  34.13 56.93 270 top
R1163  100K_2  [R0201]  34.89 56.93 270 top
R1168  3.3K_4  [R0402]  88.26 42.32 90 top
R1169  3.3K_4  [R0402]  87.29 42.32 90 top
R1178  10K_2  [R0201]  72.31 62.64 90 top
R1179  100K_2  [R0201]  74.77 43.47 180 bottom
R1180  499/F_4  [R0402]  149.32 43.09 0 bottom
R1181  *0_4  [R0402]  37.3 43.98 270 top
R1182  *0_4  [R0402]  36.16 43.98 270 top
R3491  100K_2  [R0201]  188.69 16.8 270 top
R3493  *SHORT_4  [S0402]  31.08 25.05 270 top
R3499  33/F_2  [R0201]  91.24 78 270 top
R3501  *SHORT_2  [S0201]  94.78 84.83 90 top
R3502  *SHORT_2  [S0201]  93.62 84.84 90 top
R3503  33/F_2  [R0201]  91.24 79.24 90 top
R3504  *SHORT_2  [S0201]  97.7 80.72 180 top
R3526  *SHORT_4  [S0402]  72.99 36.61 270 bottom
R3534  *SHORT_6  [S0603]  186.28 70.52 90 bottom
R3535  *SHORT_6  [S0603]  20.92 24.57 0 top
R3550  1K/F_4  [R0402]  9.75 83.73 180 top
R3571  *Short_0805  [S0805]  124.3 77.5 270 top
R3587  100K_2  [R0201]  107.92 72.55 270 top
R3591  100K/F_4  [R0402]  90.26 25.31 180 bottom
R3592  100K/F_4  [R0402]  90.26 24.29 180 bottom
R3593  47K/F_4  [R0402]  81.5 31.78 270 bottom
R3594  47K/F_4  [R0402]  78.07 31.78 270 bottom
R3596  100K/F_4  [R0402]  83.15 26.7 90 bottom
R3597  47K/F_4  [R0402]  85.16 23.4 270 bottom
R3603  *SHORT_4  [S0402]  20.67 57.82 0 top
R3604  10K_2  [R0201]  43.96 45.78 90 top
R3608  10K_2  [R0201]  39.34 49.56 90 top
R3609  1M_2  [R0201]  44.16 44.86 0 top
R3611  1M_2  [R0201]  28.8 48.67 180 top
R3614  1M_2  [R0201]  28.8 49.56 180 top
R3620  *SHORT_4  [S0402]  41.14 51.47 270 top
R4434  100K_2  [R0201]  99.98 75.21 0 top
R5004  560_4  [R0402]  10 76.61 0 top
R5009  *0_2  [R0201]  92.62 56.49 180 bottom
R5010  *SHORT_6  [S0603]  46.19 60.74 0 top
R5018  *SHORT_4  [S0402]  23.69 48.19 180 bottom
R5020  100K_2  [R0201]  190.34 22.13 270 top
R5026  *SHORT_2  [S0201]  90.14 46.13 0 bottom
R5027  *0_2  [R0201]  90.01 41.82 90 bottom
R5037  365/F_4  [R0402]  136.35 41.27 0 top
R5038  9.1K/F_4  [R0402]  18 49.64 0 top
R5039  *SHORT_4  [S0402]  19.27 53.75 0 top
R5040  *SHORT_4  [S0402]  90.39 44.36 0 bottom
R5041  *0_4  [R0402]  28.41 47.66 0 top
R5042  9.1K/F_4  [R0402]  13.68 50.07 90 top
R5043  *SHORT_4  [S0402]  13.68 51.85 90 top
R5049  *10K_4  [R0402]  90.26 26.32 0 bottom
R5050  2K/F_4  [R0402]  88.1 26.32 180 bottom
R5051  *SHORT_4  [S0402]  69.31 33.94 180 bottom
R5057  33_4  [R0402]  111.48 77.06 90 bottom
R5058  33_4  [R0402]  113.83 77.11 90 bottom
R5059  33_4  [R0402]  110.51 76.87 90 bottom
R5060  33_4  [R0402]  109.55 77.38 90 bottom
R5063  *SHORT_4  [S0402]  149.6 25.97 0 top
R5066  *SHORT_4  [S0402]  147.44 23.73 0 top
R5068  *SHORT_4  [S0402]  146.88 21.72 270 top
R5072  *SHORT_4  [S0402]  150.23 24.57 270 top
R5073  10K_4  [R0402]  151.78 25.46 90 top
R5078  *SHORT_4  [S0402]  81.37 50.58 270 bottom
R5079  *43_4  [R0402]  82.39 49.44 270 bottom
R5080  *SHORT_4  [S0402]  76.29 44.86 270 top
R5081  *0_4  [R0402]  75.15 44.86 90 top
R5084  *0_4  [R0402]  76.04 34.7 90 bottom
R5085  *0_6  [R0603]  27.65 26.2 0 top
R5086  *SHORT_6  [S0603]  27.65 27.72 0 top
R5087  *0_6  [R0603]  20.92 25.99 0 top
R5088  10K_4  [R0402]  90.72 66.17 180 top
R5090  *0_4  [R0402]  27.14 21.88 270 bottom
R5091  *0_4  [R0402]  26.13 21.88 270 bottom
R5092  *4.42K/F_4  [R0402]  24.99 29.75 0 top
R5093  *SHORT_4  [S0402]  117.24 18.45 180 top
R5094  *100K/F_4  [R0402]  115.84 18.02 90 top
R5095  100K_2  [R0201]  204.56 11.97 90 top
R5096  100K_2  [R0201]  205.45 11.97 90 top
R5097  100K_2  [R0201]  206.34 11.97 90 top
R5098  *SHORT_4  [S0402]  33.11 35.59 270 top
R5099  *SHORT_4  [S0402]  29.18 34.45 270 top
R5100  *0_4  [R0402]  31.97 35.59 90 top
R5101  *0_4  [R0402]  30.32 34.45 270 top
R5102  100K_2  [R0201]  33.11 34.07 270 top
R5103  *SHORT_4  [S0402]  201.9 14.77 90 top
R5104  *SHORT_4  [S0402]  88.99 34.75 180 bottom
R5106  100K/F_4  [R0402]  155.31 21.37 90 top
R5107  0_2  [R0201]  106.9 71.66 180 bottom
R5108  *4.7K_4  [R0402]  24.27 46.24 90 bottom
R5109  4.7K_4  [R0402]  18.46 49.26 90 bottom
R5110  *4.7K_4  [R0402]  21.38 48.06 180 bottom
R5115  *SHORT_6  [S0603]  23.26 50.63 180 top
R5116  2K/F_4  [R0402]  18.23 41.66 0 bottom
R5117  33_4  [R0402]  194.78 16.54 180 top
R5118  33_4  [R0402]  178.08 88.46 0 top
R5123  *0_4  [R0402]  24.1 49.31 180 bottom
R5124  *0_6  [R0603]  18.97 37.42 180 top
R5125  33_4  [R0402]  64.23 56.42 180 top
R5126  15_4  [R0402]  70.32 47.4 180 bottom
R5127  15_4  [R0402]  70.32 49.44 180 bottom
R5128  15_4  [R0402]  70.32 51.47 180 bottom
R5129  15_4  [R0402]  70.32 45.37 180 bottom
R5130  15_4  [R0402]  70.32 46.39 180 bottom
R5131  15_4  [R0402]  70.32 48.42 180 bottom
R5132  15_4  [R0402]  70.32 50.45 180 bottom
R5133  15_4  [R0402]  70.32 52.48 180 bottom
R5134  15_4  [R0402]  70.32 43.21 180 bottom
R5135  15_4  [R0402]  98.01 60.73 270 bottom
R5136  15_4  [R0402]  97.05 60.73 270 bottom
R5137  0_4  [R0402]  94.78 83.33 270 top
R5138  0_4  [R0402]  93.76 83.33 270 top
R5139  0_4  [R0402]  97.5 78.96 270 top
R5140  *0_4  [R0402]  101.76 40.53 270 bottom
R5141  *0_4  [R0402]  101.59 40.9 270 top
R5142  0_4  [R0402]  103.6 40.42 180 top
R5143  0_4  [R0402]  100.74 40.51 270 bottom
R5144  *0_4  [R0402]  153.79 23.43 270 top
R5145  0_4  [R0402]  154.93 23.43 270 top
R5146  10K_4  [R0402]  96.06 73.82 0 top
R5147  *0_4  [R0402]  98.51 78.96 270 top
R5148  47/F_4  [R0402]  25.11 21.5 180 top
R5149  47/F_4  [R0402]  27.14 21.5 0 top
R5150  100K/F_4  [R0402]  108.57 76.22 270 bottom
R5151  *SHORT_4  [S0402]  153.87 20.86 90 top
R5152  10K_4  [R0402]  149.22 24.57 270 top
R5153  100K/F_4  [R0402]  88.49 31.28 0 bottom
R5154  *0_4  [R0402]  48.48 64.8 0 top
R5155  *0_4  [R0402]  48.48 60.99 180 top
R5157  *10K_4  [R0402]  48.1 58.07 270 bottom
R5158  10K_4  [R0402]  39.21 57.31 0 top
R5159  0_2  [R0201]  94.71 50.07 90 bottom
R5160  2.2_6  [R0603]  178.42 83.8 0 top
R6001  *10/F_4  [R0402]  103.04 38.68 90 top
R6002  *10/F_4  [R0402]  96.88 80.98 0 bottom
R6003  *10/F_4  [R0402]  87.09 82.58 0 top
R6006  *0_4  [R0402]  40.86 61.04 180 top
R6007  *0_4  [R0402]  44.17 64.2 180 top
R6008  *10/F_4  [R0402]  93.44 90.2 0 bottom
R6009  *10/F_4  [R0402]  146.63 38.79 0 bottom
RAP1000  100K_2  [R0201]  103.22 76.23 0 top
RAP1001  10K_2  [R0201]  103.23 74.6 0 top
RAP1002  *10K_2  [R0201]  93.14 71.49 0 bottom
RAP1003  10K_2  [R0201]  101.89 42.57 0 bottom
RAP1004  100K_2  [R0201]  100.87 42.57 180 bottom
RAP1005  10K_2  [R0201]  108.04 73.82 0 top
RAP1008  100K_2  [R0201]  96.46 73.03 270 bottom
RAP1009  4.7K_2  [R0201]  86.58 52.1 180 bottom
RAP1010  4.7K_2  [R0201]  86.55 53.01 180 bottom
RAP1011  10K_2  [R0201]  108.04 74.58 0 top
RAP1013  24.9_4  [R0402]  142.46 41.05 270 bottom
RAP1014  100K_2  [R0201]  93.18 50.07 270 bottom
RAP1016  100K_2  [R0201]  93.95 50.07 270 bottom
RAP1017  162_4  [R0402]  99.84 74.84 0 bottom
RAP1018  80.6_4  [R0402]  99.84 75.85 0 bottom
RAP1019  200_4  [R0402]  99.84 76.87 0 bottom
RAP1021  24.9_4  [R0402]  171.67 82.08 180 top
RAP1023  24.9_4  [R0402]  166.37 82.08 180 top
RAP1025  24.9_4  [R0402]  168.97 82.12 180 top
RAP1026  5.11_4  [R0402]  171.67 84.36 0 top
RAP1027  10/F_4  [R0402]  166.34 84.37 0 top
RAP1028  10/F_4  [R0402]  168.97 84.41 0 top
RAP1029  8.2K/F_4  [R0402]  171.67 86.65 0 top
RAP1030  8.2K/F_4  [R0402]  171.67 85.5 180 top
RAP1031  8.2K/F_4  [R0402]  166.34 86.65 0 top
RAP1032  8.2K/F_4  [R0402]  166.34 85.51 180 top
RAP1033  8.2K/F_4  [R0402]  169 86.65 0 top
RAP1034  8.2K/F_4  [R0402]  168.97 85.55 180 top
RAP1035  *20K_2  [R0201]  90.85 63.86 90 top
RAP1044  1K_2  [R0201]  93.21 81.8 270 bottom
RAP1046  *20K_2  [R0201]  98.34 76.87 270 bottom
RAP1047  2.2K_4  [R0402]  110.98 35.84 90 top
RAP1049  2.2K_4  [R0402]  112.25 35.84 90 top
RAP1050  200_4  [R0402]  95.79 55.2 0 bottom
RAP1051  10K_2  [R0201]  96.87 51.85 180 bottom
RAP1052  10K_2  [R0201]  96.87 51.11 180 bottom
RAP1053  100/F_4  [R0402]  100.3 49.61 270 bottom
RAP1054  200_4  [R0402]  94.78 70.13 0 bottom
RAP1055  100/F_4  [R0402]  111.73 40.93 90 top
RAP1061  100K_2  [R0201]  102.28 81.21 0 bottom
RAP1062  1K_2  [R0201]  148.15 39.86 270 bottom
RAP1064  60.4_4  [R0402]  149.14 40.6 270 bottom
RAP1067  1M_2  [R0201]  113.12 72.68 270 top
RAP1072  20K_4  [R0402]  98.08 78.3 180 bottom
RAP1075  1M_4  [R0402]  92.96 75.43 180 bottom
RAP1077  10K_2  [R0201]  95.65 73.08 270 bottom
RAP1078  20K_4  [R0402]  98.09 79.33 180 bottom
RAP1081  *100K_2  [R0201]  108.04 75.34 0 top
RAP1087  1M_4  [R0402]  124.14 41.4 0 bottom
RAP1088  10M_4  [R0402]  106.27 75.75 180 bottom
RAP1089  *SHORT_4  [S0402]  124.57 39.97 270 bottom
RAP1090  *SHORT_4  [S0402]  123.54 39.96 270 bottom
RAP1091  2.7K/F_4  [R0402]  126.41 41.1 0 bottom
RAP1322  1.5K/F_4  [R0402]  104.11 39.02 270 top
RAP1323  49.9_4  [R0402]  142.59 38.95 90 bottom
RAP1324  *100K_2  [R0201]  148.14 40.97 270 bottom
RAP1325  *SHORT_2  [S0201]  147.99 69.24 180 bottom
RAP1326  *SHORT_2  [S0201]  98.95 71.69 270 bottom
RAP1327  *1K_2  [R0201]  152.11 40.29 0 bottom
RAP1328  *1K_2  [R0201]  147.54 44.1 0 bottom
RAP1330  *1K_2  [R0201]  147.52 43.06 0 bottom
RAP1331  *1K_2  [R0201]  147.54 44.86 0 bottom
RAP1332  1K_2  [R0201]  147.54 45.88 0 bottom
RAP1333  *1K_2  [R0201]  150.59 40.42 0 bottom
RAP1335  *1K_2  [R0201]  147.54 46.9 0 bottom
RAP1336  *1K_2  [R0201]  147.41 49.18 270 bottom
RAP1337  *1K_2  [R0201]  148.99 47.2 90 bottom
RAP1343  150/F_4  [R0402]  150.46 44.1 0 bottom
RAP1344  1K/F_4  [R0402]  150.46 45.12 0 bottom
RAP1351  *SHORT_4  [S0402]  139.21 40.42 180 top
RAP1352  *SHORT_4  [S0402]  139.11 41.38 180 top
RAP1360  *SHORT_2  [S0201]  104.74 9.66 180 bottom
RAP1364  *SHORT_2  [S0201]  97.38 9.3 0 bottom
RAP1376  *SHORT_4  [S0402]  137.1 37.27 0 top
RAP1377  *SHORT_4  [S0402]  137.1 38.23 0 top
RAP1381  *SHORT_4  [S0402]  139.49 39.86 90 bottom
RAP1382  *SHORT_4  [S0402]  138.52 39.89 90 bottom
RAP1383  *SHORT_4  [S0402]  140.68 37.57 0 top
RAP1384  *SHORT_4  [S0402]  140.25 38.92 90 top
RAP1385  *SHORT_4  [S0402]  93.26 83.29 270 bottom
RAP1386  *SHORT_4  [S0402]  93.52 86.04 180 bottom
RAP1387  100K/F_4  [R0402]  93.49 84.97 180 bottom
RAP1405  *SHORT_2  [S0201]  80.74 56.45 90 top
RAP1406  *SHORT_2  [S0201]  76.7 52.84 0 bottom
RAP1407  33_2  [R0201]  68.52 57.95 0 top
RAP1408  33_2  [R0201]  74.77 56.19 90 top
RAP1409  *SHORT_2  [S0201]  82.52 55.79 0 bottom
RAP1410  *SHORT_2  [S0201]  75.68 52.84 0 bottom
RAP1412  *3.3K_4  [R0402]  76.29 57.69 270 top
RAP1413  100K/F_4  [R0402]  75.15 57.69 270 top
RAP1414  100K/F_4  [R0402]  74.01 57.69 270 top
RAP1422  *SHORT_2  [S0201]  54.58 57.56 0 top
RAP1423  *4.7K_4  [R0402]  54.58 56.17 270 top
RAP1424  100K_2  [R0201]  62.86 55.05 90 top
RAP1428  *SHORT_2  [S0201]  99.15 9.43 180 bottom
RAP1429  *SHORT_2  [S0201]  100.17 18.32 90 bottom
RAP1430  100K_2  [R0201]  97.38 85.12 270 bottom
RAP1431  100K_2  [R0201]  100.52 81.73 90 top
RAP1432  *20K_2  [R0201]  97.49 72.1 0 top
RAP1433  *20K_2  [R0201]  98.29 75.73 270 bottom
RAP1434  20K_2  [R0201]  104.39 40.91 90 bottom
RAP1436  20K_2  [R0201]  105.88 40.91 90 bottom
RAP1438  20K_2  [R0201]  105.12 40.91 90 bottom
RAP1440  20K_2  [R0201]  103.65 40.91 90 bottom
RAP1450  100/F_4  [R0402]  146.78 40.93 0 bottom
RAP1451  56_4  [R0402]  146.78 39.91 180 bottom
RAP1452  10K_2  [R0201]  101.77 75.71 180 bottom
RAP1453  100K_2  [R0201]  103.6 42.58 0 bottom
RAP1455  100K_2  [R0201]  97.5 40.55 270 bottom
RAP1457  *SHORT_2  [S0201]  107.66 77.76 270 top
RAP1458  *0_2  [R0201]  108.04 76.87 180 top
RAP1459  *SHORT_2  [S0201]  93.12 72.31 180 bottom
RAP3020  1M_2  [R0201]  108.04 76.11 0 top
RAP3021  *3.3K_4  [R0402]  64.23 58.58 0 top
RAP3023  *3.3K_4  [R0402]  64.23 59.98 0 top
RAP3040  1M_4  [R0402]  91.66 41.87 180 bottom
RAP3041  1M_4  [R0402]  75.02 34.7 270 bottom
RAP3042  *10K_2  [R0201]  72.76 39.76 90 top
RAP3043  *4.7K_4  [R0402]  112.23 33.94 270 top
RAP3044  *4.7K_4  [R0402]  110.96 33.94 270 top
RAP3045  0_4  [R0402]  91.91 89.06 90 top
RAP3046  *0_4  [R0402]  90.9 89.06 90 top
RAP3047  *100K_2  [R0201]  92.68 90.33 180 top
RAP3048  *0_4  [R0402]  98.01 89.7 270 top
RAP3049  10K_2  [R0201]  96.99 89.06 0 bottom
RAP3051  *0_2  [R0201]  95.85 89.06 180 bottom
RAP3052  *0_2  [R0201]  101.47 76.89 270 bottom
RAP3053  4.7K_2  [R0201]  100.17 52.48 0 bottom
RAP3054  4.7K_2  [R0201]  100.17 53.37 0 bottom
RCP4021  100K_2  [R0201]  175.23 20.48 270 top
RCP4029  100K_2  [R0201]  29.18 27.21 270 bottom
RCP4037  10K_2  [R0201]  172.94 23.78 270 bottom
RCP4072  *SHORT_4  [S0402]  89.25 14.38 90 bottom
RCP4074  *0_4  [R0402]  86.58 16.57 270 bottom
RCP4160  100K/F_4  [R0402]  19.65 57.69 180 bottom
RCP4162  100K/F_4  [R0402]  21.56 57.69 0 bottom
RCP4184  2M/F_4  [R0402]  16.81 59.01 180 bottom
RCP4186  2M/F_4  [R0402]  16.81 60.15 180 bottom
RCP4190  100K_2  [R0201]  27.4 27.21 90 bottom
RCP4191  100K_2  [R0201]  26.51 27.21 90 bottom
RCP4193  30K/F_4  [R0402]  30.07 34.32 270 bottom
RCP4194  48.7K_4  [R0402]  29.05 34.32 270 bottom
RCP4216  *SHORT_2  [S0201]  119.47 19.46 270 top
RCP4219  100K/F_4  [R0402]  23.21 59.98 180 top
RCP4220  100K/F_4  [R0402]  20.16 68.11 90 bottom
RCP4221  100K_2  [R0201]  203.47 12 270 top
RPM3123  10K_4  [R0402]  86.96 32.8 270 bottom
RPM3282  *SHORT_6  [S0603]  90.44 56.47 0 top
RPM3283  *Short_0805  [S0805]  91.02 59.51 0 top
RPM3284  *SHORT_6  [S0603]  92.68 52.87 270 top
RPM3285  *SHORT_4  [S0402]  100.27 38.54 90 top
RPM3286  *Short_0805  [S0805]  90.54 50.3 0 top
RPM3287  *SHORT_4  [S0402]  104.61 31.78 90 bottom
RPM3288  *SHORT_4  [S0402]  90.29 52.2 0 top
RPM3289  *Short_0805  [S0805]  95.09 54.62 0 top
RPM3290  *SHORT_4  [S0402]  91.08 61.55 0 top
RPM3291  *SHORT_4  [S0402]  107.03 40.29 180 top
RPM3292  *SHORT_4  [S0402]  90.61 57.71 0 top
RPM3293  *SHORT_4  [S0402]  108.55 40.93 90 top
RPM3294  *SHORT_4  [S0402]  102.46 32.42 90 bottom
RPM3295  *SHORT_4  [S0402]  109.57 40.93 90 top
RPM3296  *SHORT_4  [S0402]  103.6 32.42 90 bottom
RPM3297  *SHORT_4  [S0402]  108.04 32.16 0 bottom
RPM3298  *SHORT_4  [S0402]  107.15 40.8 0 bottom
RPM3305  *SHORT_4  [S0402]  92.64 57.71 0 top
RPM3309  *SHORT_4  [S0402]  98.07 83.08 0 top
RPM3310  *0.01/F_4  [R0402]  98.07 84.1 180 top
RPM3312  *SHORT_4  [S0402]  104.11 73.21 270 top
RPM3314  *SHORT_4  [S0402]  97.49 73.68 270 top
RPM3315  *SHORT_4  [S0402]  98.58 85.11 0 top
RPM3316  *SHORT_4  [S0402]  100.37 73.62 270 top
RPM3317  *SHORT_4  [S0402]  110.71 71.28 270 top
RPM3323  *0.01/F_4  [R0402]  89.06 55.9 180 bottom
RPM3324  *SHORT_4  [S0402]  87.11 57.13 90 bottom
RPM3326  *SHORT_4  [S0402]  99.36 73.62 270 top
RPM3327  *SHORT_4  [S0402]  93.1 73.33 0 bottom
RPM3328  *SHORT_4  [S0402]  89.01 54.86 0 bottom
RPM3329  *SHORT_4  [S0402]  92.91 58.88 0 bottom
RPM3331  *SHORT_4  [S0402]  92.56 57.35 0 bottom
RPM3333  *SHORT_4  [S0402]  89.53 57.79 0 bottom
RPM3337  2.2_6  [R0603]  83.02 35.47 270 top
RPM3338  *SHORT_4  [S0402]  95.09 18.68 180 bottom
RPM3426  10K_2  [R0201]  74.77 41.82 0 bottom
RPM3427  20K_2  [R0201]  81.63 45.88 90 top
RPM3429  22_2  [R0201]  92.74 76.45 180 bottom
RPM3431  *SHORT_4  [S0402]  72.99 40.93 270 bottom
RPM3452  10K_2  [R0201]  90.14 45.37 180 bottom
RPM3453  10M_4  [R0402]  78.83 48.55 180 top
RPM3455  *SHORT_2  [S0201]  86.96 44.23 90 top
RPM3457  100K_2  [R0201]  68.52 57.06 0 top
RPM3458  2.2K_4  [R0402]  83.91 49.11 270 top
RPM3460  *SHORT_4  [S0402]  87.98 35.09 270 top
RPM3461  *SHORT_4  [S0402]  98.77 26.53 180 bottom
RPM3462  *SHORT_4  [S0402]  87.98 32.8 270 bottom
RPM3463  *SHORT_4  [S0402]  98.39 27.85 180 bottom
RPM3465  100K_2  [R0201]  77.18 34.2 180 bottom
RPM3467  2.2K_4  [R0402]  82.77 49.11 270 top
RPM3468  10K_2  [R0201]  88.49 28.1 180 bottom
RPM3470  3.3K_4  [R0402]  87.22 40.42 90 top
RPM3472  3.3K_4  [R0402]  88.49 40.42 90 top
RPM3473  10K_2  [R0201]  95.85 27.59 90 top
RPM3475  4.7K_4  [R0402]  88.36 37.75 270 top
RPM3476  4.7K_4  [R0402]  87.38 37.75 270 top
RPM3558  220_4  [R0402]  145.02 40.4 180 bottom
RPM3562  100K_2  [R0201]  89.88 40.42 90 bottom
RPM3573  100K/F_4  [R0402]  82.64 31.78 270 bottom
RPM3576  4.7K_4  [R0402]  99.15 18.45 270 bottom
RPM3577  4.7K_4  [R0402]  100.68 9.43 0 bottom
RPM3578  33_4  [R0402]  88.49 28.99 180 bottom
RPM3579  33_4  [R0402]  88.99 32.8 270 bottom
RPM3580  33_4  [R0402]  89.12 35.09 270 top
RPM3581  33_4  [R0402]  88.49 30.13 180 bottom
RPM3589  *0_4  [R0402]  172.69 19.59 180 top
RPM3590  0_4  [R0402]  172.69 20.61 180 top
RPM3591  *3.3K_4  [R0402]  81.42 72.98 90 top
RPM3592  *3.3K_4  [R0402]  81.04 74.66 180 top
RSM1012  243_4  [R0402]  146.8 89.28 90 top
RSM1014  243_4  [R0402]  146.8 87.56 270 top
RSM2007  243_4  [R0402]  163.05 78.06 90 top
RSM2008  243_4  [R0402]  163.05 76.33 270 top
RSM2075  243_4  [R0402]  122.8 90.15 180 top
RSM2076  243_4  [R0402]  122.8 89.14 180 top
RSM2112  243_4  [R0402]  103.29 90.3 180 top
RSM2113  243_4  [R0402]  103.29 89.16 180 top
RSM2143  20K_2  [R0201]  68.93 47.28 90 bottom
RSM2144  20K_2  [R0201]  68.93 49.56 90 bottom
RSM2145  20K_2  [R0201]  68.93 51.72 90 bottom
RSM2146  20K_2  [R0201]  68.93 44.99 90 bottom
RSM2147  20K_2  [R0201]  68.93 46.13 270 bottom
RSM2148  20K_2  [R0201]  68.93 48.42 270 bottom
RSM2149  20K_2  [R0201]  68.93 50.58 270 bottom
RSM2150  20K_2  [R0201]  64.48 56.68 90 bottom
RSM2151  20K_2  [R0201]  68.93 52.87 270 bottom
RSM2152  20K_2  [R0201]  68.93 53.88 90 bottom
RSM2155  20K_2  [R0201]  68.93 43.72 270 bottom
SW1  *Power Switch  [SW-TME-533B-Q-TR-6P]  113.78 14.38 90 bottom
TP17  *  [TP2050]  111.73 73.44 180 bottom
TP18  *  [TP2050]  108.3 70.9 0 top
TP20  *  [TP2050]  111.58 72.16 180 bottom
TP21  *  [TP2050]  104.21 73.44 180 bottom
TP22  *  [TP2050]  108.47 62.32 180 top
TP23  *  [TP2050]  135.68 40.77 180 bottom
TP24  *  [TP2050]  136.97 40.15 180 bottom
TP33  *  [TP2050]  129.49 61.8 0 top
TP34  *  [TP2050]  99.81 71.28 180 top
TP39  *  [TP2050]  150.89 46.77 180 bottom
TP48  *  [TP2050]  118.42 61.8 180 top
TP49  *  [TP2050]  116.62 61.74 180 top
TP51  *  [TP2050]  109.57 61.63 0 top
TP52  *  [TP2050]  111.06 62.4 180 top
TP57  *  [TP2050]  35.15 54.14 270 top
TP61  *  [TP2050]  26.87 47.12 180 top
TP63  *  [TP2050]  69.9 75.65 270 top
TP71  *  [TP2050]  66.39 74.86 0 top
TP75  *  [TP2050]  110.71 74.33 0 bottom
TP76  *  [TP2050]  101.26 72.19 0 bottom
TP77  *  [TP2050]  106.93 72.98 0 bottom
TP78  *  [TP2050]  99.74 71.25 0 bottom
TP79  *  [TP2050]  109.23 72.16 0 bottom
TP80  *  [TP2050]  107.26 61.88 90 top
TP81  *  [TP2050]  103.47 9.69 180 bottom
TP82  *  [TP2050]  102.2 9.69 180 bottom
TP83  *  [TP2050]  98.26 9.3 180 bottom
TP84  *  [TP2050]  96.36 9.84 180 bottom
TP85  *  [TP2050]  95.09 9.84 180 bottom
TP86  *  [TP2050]  97.05 17.33 180 bottom
TP87  *  [TP2050]  98.14 18.58 180 bottom
TP88  *  [TP2050]  98.34 17.31 180 bottom
TP89  *  [TP2050]  102.33 19.21 180 bottom
TP90  *  [TP2050]  102.46 17.69 180 bottom
TP91  *  [TP2050]  102.33 20.61 180 bottom
TP98  *  [TP2050]  149.06 42.07 0 bottom
TP100  *  [TP2050]  91.06 71.38 180 top
TP101  *  [TP2050]  53.38 67.85 0 top
TP102  *  [TP2050]  110.05 73.16 0 bottom
TP106  *  [TP2050]  65.24 76.87 0 top
TP107  *  [TP2050]  64.08 79.66 0 top
TP108  *  [TP2050]  76.62 83.6 180 bottom
TP109  *  [TP2050]  65.07 80.55 0 top
TP110  *  [TP2050]  65.8 78.72 0 top
TP111  *  [TP2050]  66.51 76.13 0 top
TP112  *  [TP2050]  62.6 74.99 180 bottom
TP113  *  [TP2050]  68.45 74.24 0 top
TP114  *  [TP2050]  67.94 75.71 0 top
TP115  *  [TP2050]  71.42 79.14 0 top
TP116  *  [TP2050]  73.5 76.22 0 top
TP117  *  [TP2050]  75.86 78.39 0 top
TP118  *  [TP2050]  72.86 77.66 0 top
TP120  *  [TP2050]  111.98 72.68 180 top
TP125  *  [TP2050]  199.79 37.19 0 top
TP127  *  [TP2050]  200.55 38.23 0 top
TP131  *  [TP2050]  104.21 72.17 0 bottom
TP136  *  [TP2050]  70.17 81.37 180 top
TP137  *  [TP2050]  98.1 50.82 0 bottom
TP138  *  [TP2050]  96.89 50.36 0 bottom
TP139  *  [TP2050]  99.28 50.12 0 bottom
TP140  *  [TP2050]  97.33 56.65 0 bottom
TP141  *  [TP2050]  96.06 56.8 0 bottom
TP142  *  [TP2050]  95.62 50.3 0 bottom
TP143  *  [TP2050]  16.71 59.67 270 top
TP146  *  [TP2050]  16.1 57.06 270 top
TP147  *  [TP2050]  39.21 48.04 180 top
TP148  *  [TP2050]  134.45 41.14 0 bottom
TP159  *  [TP2050]  20.29 71.41 90 top
TP160  *  [TP2050]  69.43 78.2 180 top
TP165  *  [TP2050]  62.2 83.09 0 top
TP167  *  [TP2050]  53.08 28.56 180 bottom
TP168  *  [TP2050]  46.18 27.59 180 bottom
TP169  *  [TP2050]  170.78 22.89 180 bottom
TP170  *  [TP2050]  176.88 24.42 180 bottom
TP171  *  [TP2050]  178.27 24.42 180 bottom
TP172  *  [TP2050]  18.41 65.26 90 top
TP177  *  [TP2050]  93.57 61.04 0 top
TP178  *  [TP2050]  92.09 62.57 0 top
TP179  *  [TP2050]  91.62 63.82 0 top
TP180  *  [TP2050]  90.8 62.59 0 top
TP189  *  [TP2050]  80.28 38.34 0 top
TP190  *  [TP2050]  76.93 47.3 0 top
TP191  *  [TP2050]  98.46 57.35 180 bottom
TP202  *  [TP2050]  85.95 45.75 0 top
TP204  *  [TP2050]  85.39 40.6 0 top
TP211  *  [TP2050]  90.04 43.52 180 bottom
TP212  *  [TP2050]  99.26 54.24 180 bottom
TP213  *  [TP2050]  100.55 54.14 180 bottom
TP221  *  [TP2050]  103.09 74.07 180 bottom
TP222  *  [TP2050]  101.95 73.29 180 bottom
TP223  *  [TP2050]  101.95 74.81 180 bottom
TP224  *  [TP2050]  102.56 72.17 180 bottom
TP225  *  [TP2050]  94.2 71.03 0 top
TP230  *  [TP2050]  134.5 38.78 0 top
TP231  *  [TP2050]  134.3 40.51 0 top
TP232  *  [TP2050]  79.21 34.07 180 bottom
TP233  *  [TP2050]  99.58 59.41 180 bottom
TP238  *  [TP2050]  133.42 71.84 0 top
TP242  *  [TP2050]  99.74 69.91 180 bottom
TP243  *  [TP2050]  112.11 21.12 180 bottom
TP244  *  [TP2050]  115.66 9.3 180 bottom
TP245  *  [TP2050]  35.02 55.41 0 top
TP246  *  [TP2050]  80.1 43.04 0 top
TP249  *  [TP2050]  81.63 38.13 0 top
TP250  *  [TP2050]  61.82 50.96 270 top
TP251  *  [TP2050]  60.55 50.96 270 top
TP252  *  [TP2050]  115.92 21.5 0 top
TP253  *  [TP2050]  105.22 41.97 180 bottom
TP254  *  [TP2050]  110.27 58.16 0 top
TP255  *  [TP2050]  139.13 41.23 180 bottom
TP256  *  [TP2050]  139.92 38.26 180 bottom
TP257  *  [TP2050]  151.78 48.22 180 bottom
TP258  *  [TP2050]  152.62 41.69 180 bottom
TP259  *  [TP2050]  149.29 48.72 180 bottom
TP260  *  [TP2050]  149.5 49.99 180 bottom
TP261  *  [TP2050]  152.09 49.49 180 bottom
TP262  *  [TP2050]  150.77 49.99 180 bottom
TP263  *  [TP2050]  147.92 48.06 180 bottom
TP264  *  [TP2050]  143.98 40.8 0 top
TP265  *  [TP2050]  145.64 40.8 0 top
TP266  *  [TP2050]  153.89 41.69 180 bottom
TP267  *  [TP2050]  155.16 41.69 180 bottom
TP268  *  [TP2050]  138.65 38.26 180 bottom
TP269  *  [TP2050]  137.38 38.08 180 bottom
TP271  *  [TP2050]  140.4 41.56 180 bottom
TP272  *  [TP2050]  144.24 39.4 0 top
TP273  *  [TP2050]  145.51 39.4 0 top
TP274  *  [TP2050]  98.19 58.28 0 top
TP275  *  [TP2050]  91.15 49.69 180 bottom
TP276  *  [TP2050]  89.63 50.07 180 bottom
TP277  *  [TP2050]  99.03 55.68 0 top
